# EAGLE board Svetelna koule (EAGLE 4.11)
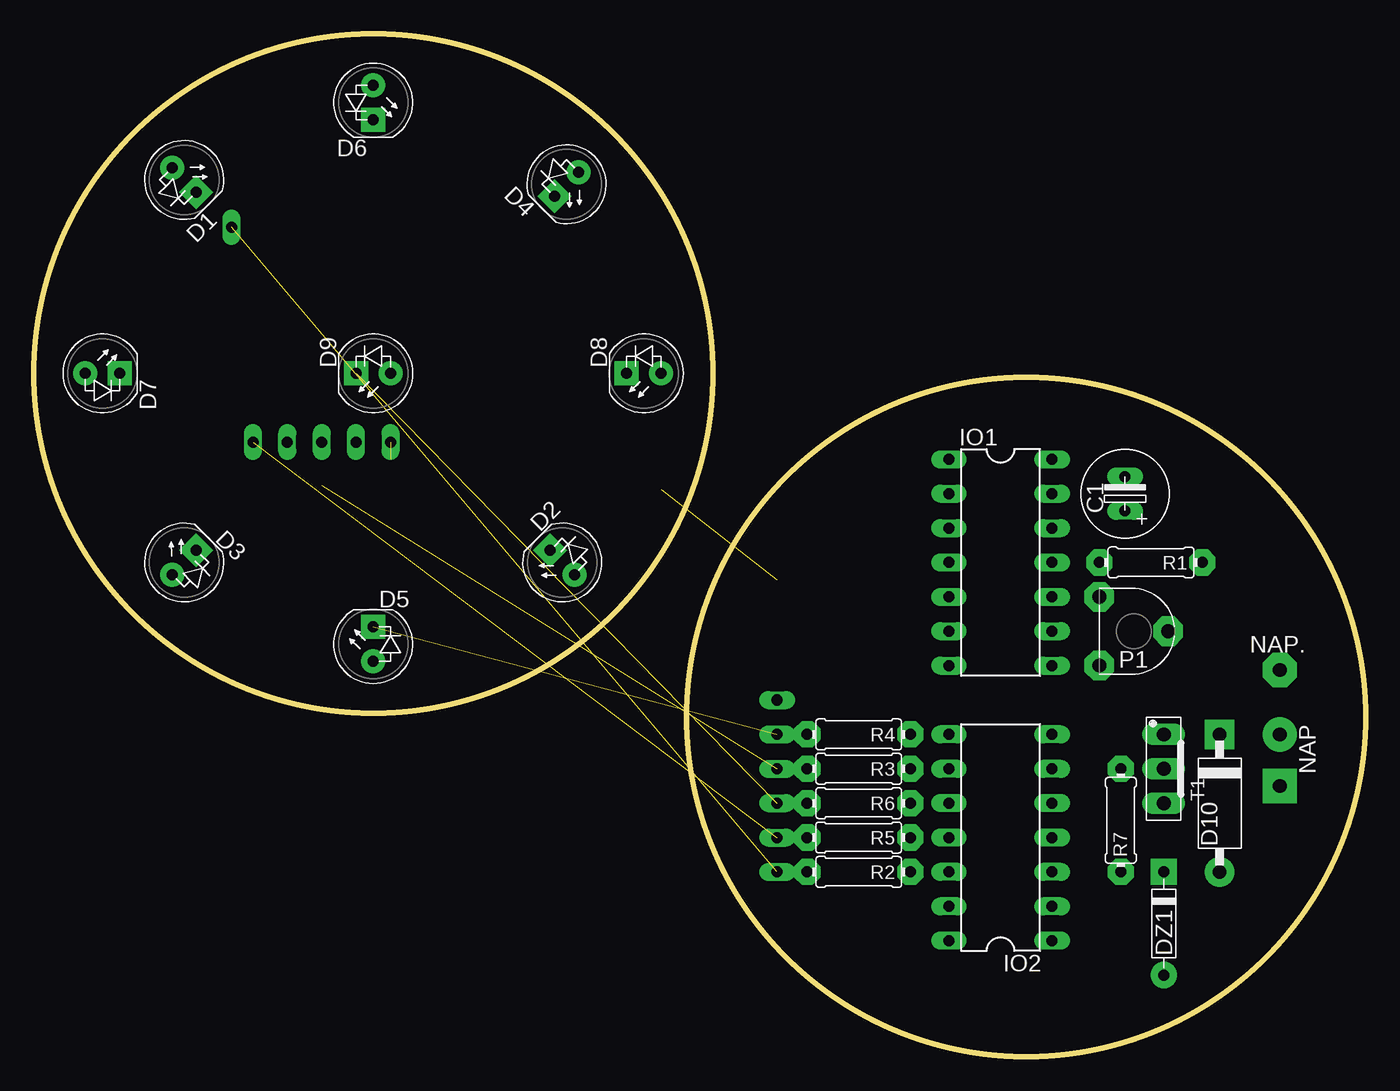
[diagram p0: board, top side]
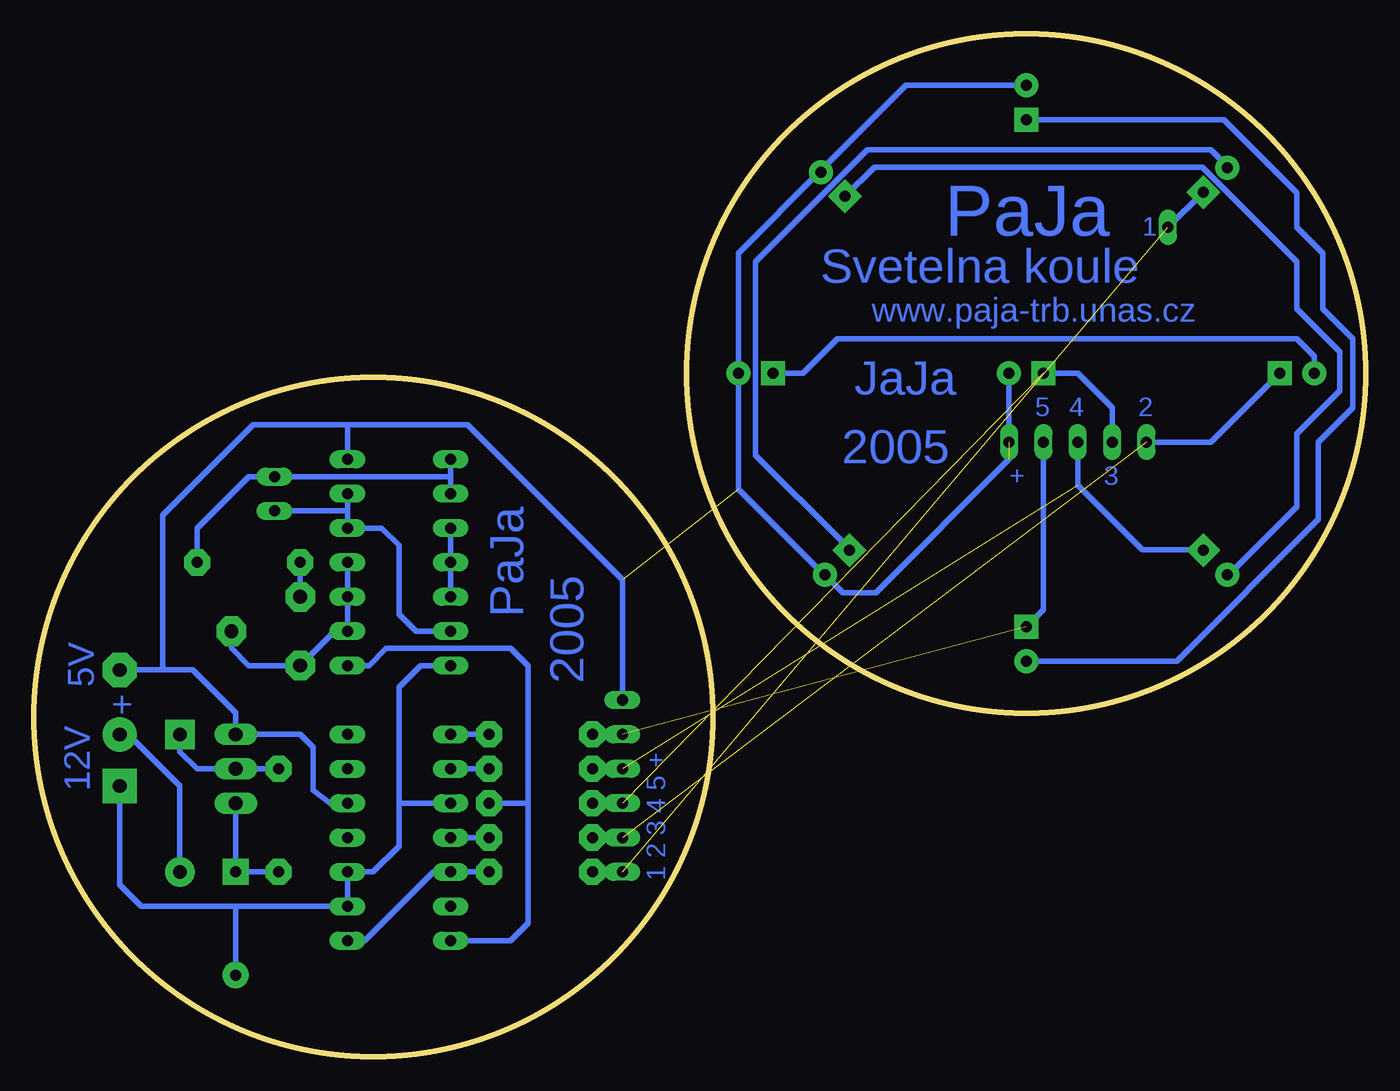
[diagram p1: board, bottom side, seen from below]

Size 98.42 x 75.56 mm. Coordinates in mm from the lower left corner, seen from the top.
Outline: circle at 25.08,50.48 radius 25.08
Outline: circle at 73.34,25.08 radius 25.08
Copper layers (1*16): Top 0.035mm / dielectric 1.5mm / Bottom 0.035mm
Design rules "default": minimum track width 10mil, minimum drill 24mil, track to track 8mil, track to pad 8mil, pad to pad 8mil, via to via 8mil, smd to smd 8mil, copper to edge 40mil, drill to drill 8mil, minimum pad ring 10mil, minimum via ring 8mil, stop-mask expansion 4mil, vias tented up to drill 0mil, thermal gap 10mil

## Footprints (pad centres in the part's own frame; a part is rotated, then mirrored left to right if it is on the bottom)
C_EL_2,5 = drill 0.813 pad 1.27 long: C+ -1.27,0; C- 1.27,0
LED_5 = drill 0.813 pad 1.778 round: A -1.27,0 | drill 0.813 pad 1.778 square: K 1.27,0
D-10 = drill 1.016 pad 2.184 round: A -5.08,0 | drill 1.016 pad 2.184 square: K 5.08,0
D-7,5 = drill 0.813 pad 1.93 round: A -3.81,0 | drill 0.813 pad 1.93 square: K 3.81,0
DIL14 = drill 0.813 long: 1 -7.62,-3.81; 2 -5.08,-3.81; 3 -2.54,-3.81; 4 0,-3.81; 5 2.54,-3.81; 6 5.08,-3.81; 7 7.62,-3.81; 8 7.62,3.81; 9 5.08,3.81; 10 2.54,3.81; 11 0,3.81; 12 -2.54,3.81; 13 -5.08,3.81; 14 -7.62,3.81
PAD_2+- = drill 1.016 pad 2.54 round: + -1.905,0 | drill 1.016 pad 2.54 square: - 1.905,0
PAD_1 = drill 1.016 pad 2.54 octagon: 1 0,0
PT6V = drill 1.016 pad 2.184 octagon: 1 -2.54,-2.54; 2 2.54,-2.54; 3 0,2.54
PAD_1--- = drill 0.813 pad 1.27 long: 1 0,0
R-7,5 = drill 0.813 pad 1.93 octagon: 1 -3.81,0; 2 3.81,0
TO-126S = drill 1.016 pad 1.6 long: 1 -2.54,0; 2 0,0; 3 2.54,0

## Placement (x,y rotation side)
C1  100M  [C_EL_2,5]  80.64,41.59 90 top
D1  c  [LED_5]  11.11,64.77 315 top
D2  z  [LED_5]  39.05,36.51 135.1 top
D3  o  [LED_5]  11.11,36.51 45.1 top
D4  zl  [LED_5]  39.37,64.45 225 top
D5  zl  [LED_5]  25.08,30.48 90 top
D6  o  [LED_5]  25.08,70.48 270 top
D7  z  [LED_5]  5.08,50.48 0 top
D8  c  [LED_5]  45.08,50.48 180 top
D9  m  [LED_5]  25.08,50.48 180 top
D10  1N4007  [D-10]  87.63,18.73 90 top
DZ1  5V6  [D-7,5]  83.5,9.84 90 top
IO1  MH7400  [DIL14]  71.44,36.51 270 top
IO2  MH7493  [DIL14]  71.44,16.19 90 top
NAP  12V  [PAD_2+-]  92.08,21.91 270 top
NAP.  5V  [PAD_1]  92.08,28.57 0 top
P1  5k  [PT6V]  81.28,31.43 270 top
PAD1  PAD_1---  [PAD_1---]  54.93,13.65 0 top
PAD2  PAD_1---  [PAD_1---]  54.93,26.35 0 top
PAD3  PAD_1---  [PAD_1---]  54.93,21.27 0 top
PAD4  PAD_1---  [PAD_1---]  54.93,23.81 0 top
PAD5  PAD_1---  [PAD_1---]  54.93,16.19 0 top
PAD6  PAD_1---  [PAD_1---]  54.93,18.73 0 top
PAD7  PAD_1---  [PAD_1---]  14.61,61.28 90 top
PAD8  PAD_1---  [PAD_1---]  16.19,45.4 90 top
PAD9  PAD_1---  [PAD_1---]  21.27,45.4 90 top
PAD10  PAD_1---  [PAD_1---]  23.81,45.4 90 top
PAD11  PAD_1---  [PAD_1---]  18.73,45.4 90 top
PAD12  PAD_1---  [PAD_1---]  26.35,45.4 270 top
R1  470  [R-7,5]  82.55,36.51 180 top
R2  100  [R-7,5]  60.96,13.65 180 top
R3  100  [R-7,5]  60.96,21.27 180 top
R4  100  [R-7,5]  60.96,23.81 180 top
R5  100  [R-7,5]  60.96,16.19 180 top
R6  220  [R-7,5]  60.96,18.73 180 top
R7  1k5  [R-7,5]  80.33,17.46 90 top
T1  BD139  [TO-126S]  83.5,21.27 270 top

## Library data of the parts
C1 = #PaJa_C-el
D1-D8 D10 DZ1 NAP NAP. P1 PAD1-PAD5 R2-R5 R7 T1 = #PaJa_11
D9 PAD6-PAD12 R1 R6 = #PaJa_111
IO1 IO2 = 74xx-eu

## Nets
1: D1.K PAD1.1 PAD7.1 R2.2
2: D7.K PAD5.1 PAD8.1 R5.2
3: D3.K PAD3.1 PAD9.1 R3.2
4: D5.K PAD4.1 PAD10.1 R4.2
5: D9.K PAD6.1 PAD11.1 R6.2
GND: DZ1.A IO1.7 IO2.2 IO2.3 IO2.10 NAP.-
N$1: IO1.9 IO1.10 IO1.11 P1.2 P1.3
N$2: DZ1.K R7.1 T1.3
N$3: C1.C+ IO1.6 IO1.12 IO1.13
N$4: C1.C- IO1.1 IO1.2 R1.1
N$5: IO2.1 IO2.12 R2.1
N$6: IO1.8 IO2.14 R6.1
N$7: IO1.3 IO1.4 IO1.5
N$12: D7.A D8.K
N$13: D3.A D4.K
N$14: D5.A D6.K
N$15: D1.A D2.K
N$16: IO2.9 R3.1
N$17: IO2.8 R4.1
N$18: IO2.11 R5.1
N$19: P1.1 R1.2
N$23: D10.K R7.2 T1.2
N$24: D10.A NAP.+
VCC: D2.A D4.A D6.A D8.A D9.A IO1.14 IO2.5 NAP..1 PAD2.1 PAD12.1 T1.1

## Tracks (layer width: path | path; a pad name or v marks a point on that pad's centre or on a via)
1  (1 unrouted)
  Bottom 0.406: D1.K PAD7.1 | PAD7.1 | PAD1.1 R2.2
2  (1 unrouted)
  Bottom 0.406: D7.K 11.43,45.4 PAD8.1 | PAD5.1 R5.2
3  (1 unrouted)
  Bottom 0.406: PAD3.1 R3.2 | PAD9.1 21.27,42.23 16.51,37.47 12.06,37.47 D3.K
4  (1 unrouted)
  Bottom 0.406: PAD4.1 R4.2 | D5.K 23.81,33.02 PAD10.1
5  (1 unrouted)
  Bottom 0.406: PAD6.1 R6.2 | D9.K 21.27,50.48 18.73,47.94 PAD11.1
GND
  Bottom 0.406: IO1.7 69.85,28.89 71.44,27.3 71.44,18.73 | IO2.10 71.44,18.73 | 71.44,18.73 71.44,15.56 73.34,13.65 IO2.3 IO2.2 83.5,11.11 | 83.5,11.11 DZ1.A | 83.5,11.11 90.49,11.11 92.08,12.7 NAP.-
N$1
  Bottom 0.406: IO1.11 IO1.10 IO1.9 76.2,31.43 P1.2 82.55,28.89 83.82,30.16 P1.3
N$2
  Bottom 0.406: R7.1 DZ1.K T1.3
N$3
  Bottom 0.406: 75.25,40.32 IO1.12 72.71,39.05 71.44,37.78 71.44,32.7 70.17,31.43 IO1.6 | 75.25,40.32 IO1.13 | 75.25,40.32 C1.C+
N$4
  Bottom 0.406: 67.63,42.86 IO1.1 | IO1.2 67.63,42.86 | 67.63,42.86 C1.C- 82.55,42.86 86.36,39.05 R1.1
N$5
  Bottom 0.406: R2.1 IO2.12 68.9,13.65 73.98,8.57 IO2.1
N$6
  Bottom 0.406: IO2.14 63.18,8.57 61.91,9.84 61.91,18.73 | 61.91,18.73 61.91,28.89 63.18,30.16 72.39,30.16 73.66,28.89 IO1.8 | 61.91,18.73 R6.1
N$7
  Bottom 0.406: IO1.5 IO1.4 IO1.3
N$12
  Bottom 0.406: D8.K 41.59,50.48 39.05,53.02 5.08,53.02 3.81,51.75 D7.A
N$13
  Bottom 0.406: D4.K 36.3,65.72 12.06,65.72 5.08,58.74 5.08,55.25 1.9,52.07 1.9,49.21 5.08,46.04 5.08,40.64 10.16,35.56 D3.A
N$14
  Bottom 0.406: D5.A 13.97,29.21 3.49,39.69 3.49,44.77 3.49,45.4 0.95,47.94 0.95,53.02 3.17,55.25 3.17,59.37 5.08,61.28 5.08,63.82 10.48,69.21 D6.K
N$15
  Bottom 0.406: D2.K 38.53,37.78 38.73,37.78 38.73,38.1 45.08,44.45 45.08,58.74 36.83,66.99 11.43,66.99 10.21,65.78 D1.A
N$16
  Bottom 0.406: R3.1 IO2.9
N$17
  Bottom 0.406: R4.1 IO2.8
N$18
  Bottom 0.406: R5.1 IO2.11
N$19
  Bottom 0.406: P1.1 R1.2
N$23
  Bottom 0.406: R7.2 T1.2 86.36,21.27 87.63,22.54 D10.K
N$24
  Bottom 0.406: D10.A 87.63,20 91.44,23.81 NAP.+
VCC  (2 unrouted)
  Bottom 0.406: D8.A 46.67,50.48 | 40.32,65.41 46.36,59.37 D8.A | D8.A 46.36,41.91 40,35.56 D2.A 38.63,34.29 36.19,34.29 26.35,44.13 D9.A | 40.32,65.41 D4.A | D6.A 33.97,71.76 40.32,65.41 | 88.9,28.58 NAP..1 | 88.9,28.58 88.9,40.01 82.23,46.67 75.25,46.67 | IO2.5 76.52,18.73 77.79,19.69 77.79,22.86 78.74,23.81 T1.1 83.5,25.4 86.68,28.58 88.9,28.58 | 75.25,46.67 IO1.14 | 75.25,46.67 66.36,46.67 59.69,40.01 54.93,35.24 PAD2.1

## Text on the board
Bottom: 1 | PaJa | Svetelna koule | www.paja-trb.unas.cz | JaJa | 2 | 4 | 5 | 2005 | 3 | + | PaJa | 2005 | 5V | + | 12V | 1 2 3 4 5 +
